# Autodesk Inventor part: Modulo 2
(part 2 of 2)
feature "Pattern of M2.44:82"
body "Solid191"
feature "Pattern of M2.44:83"
body "Solid192"
feature "Pattern of M2.44:84"
body "Solid193"
feature "Pattern of M2.44:85"
body "Solid194"
feature "Pattern of M2.44:86"
body "Solid195"
feature "Pattern of M2.44:87"
body "Solid196"
feature "Pattern of M2.44:88"
body "Solid197"
feature "Pattern of M2.44:89"
body "Solid198"
feature "Pattern of M2.44:90"
body "Solid199"
feature "Pattern of M2.44:91"
body "Solid200"
feature "Pattern of M2.44:92"
body "Solid201"
feature "Pattern of M2.44:93"
body "Solid202"
feature "Pattern of M2.44:94"
body "Solid203"
feature "Pattern of M2.44:95"
body "Solid204"
feature "Pattern of M2.44:96"
body "Solid205"
feature "Pattern of M2.44:97"
body "Solid206"
feature "Pattern of M2.44:98"
body "Solid207"
feature "Pattern of M2.44:99"
body "Solid208"
feature "Pattern of M2.44:100"
body "Solid209"
feature "Pattern of M2.44:101"
body "Solid210"
feature "Pattern of M2.44:102"
body "Solid211"
feature "Pattern of M2.44:103"
body "Solid212"
body "Solid213"
body "Solid214"
body "Solid215"
body "Solid216"
body "Solid217"
body "Solid218"
body "Solid219"
body "Solid220"
body "Solid221"
body "Solid222"
body "Solid223"
body "Solid224"
body "Solid225"
body "Solid226"
body "Solid227"
body "Solid228"
body "Solid229"
body "Solid230"
body "Solid231"
body "Solid232"
body "Solid233"
body "Solid234"
body "Solid235"
body "Solid236"
body "Solid237"
body "Solid238"
body "Solid239"
body "Solid240"
body "Solid241"
body "Solid242"
body "Solid243"
body "Solid244"
body "Solid245"
body "Solid246"
body "Solid247"
body "Solid248"
body "Solid249"
body "Solid250"
body "Solid251"
body "Solid252"
body "Solid253"
body "Solid254"
body "Solid255"
body "Solid256"
body "Solid257"
body "Solid258"
body "Solid259"
body "Solid260"
body "Solid261"
body "Solid262"
body "Solid263"
body "Solid264"
body "Solid265"
node "Cimento"
move_body "Move1" dims "d414" = -10
move_body "Move2" dims "d417" = -10
other parameters: "T_P_L" = 115 [user parameter; used in 102 equation terms], "T_P_P" = 58 [user parameter; used in 15 equation terms], "A_P_L" = 115 [user parameter], "A_P_P" = 58 [user parameter], "d267" = 15, "d412" = 0, "d413" = 0, "d415" = 0, "d416" = 0
